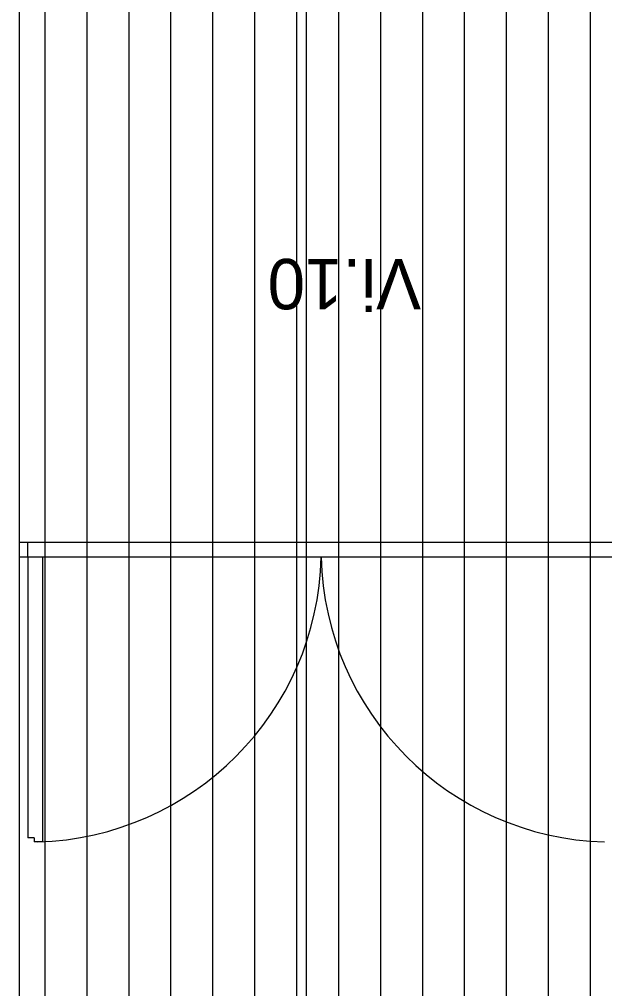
# Model space of a CAD drawing. Extents: x 1278 to 1356, y -253.7 to -224.
# Drawn here: x 1307.602 to 1308.997, y -239.071 to -236.76 of the extents above; entities that cross this region are included whole.
import ezdxf

# ---------------------------------------------------------------- set-up
doc = ezdxf.new("R2010")
doc.units = 0
for name, color, linetype in [('Level 10', 7, 'Continuous'), ('Level 13', 7, 'Continuous'), ('Level 4', 7, 'Continuous'), ('Level 40', 7, 'Continuous'), ('Level 65', 7, 'Continuous'), ('Level 93', 7, 'Continuous')]:
    doc.layers.add(name, color=color, linetype=linetype)

msp = doc.modelspace()

# ---------------------------------------------------------------- linework, layer by layer
at = {"layer": 'Level 10'}
for p, q in [((1307.6633, -243.574), (1307.6633, -235.1552)), ((1307.7633, -243.574), (1307.7633, -235.1552)), ((1307.8633, -243.574), (1307.8633, -235.1552)), ((1307.9633, -243.574), (1307.9633, -235.1552)), ((1308.0633, -243.574), (1308.0633, -235.1552)), ((1308.1633, -243.574), (1308.1633, -235.1552)), ((1308.2633, -243.574), (1308.2633, -235.1552)), ((1308.3633, -243.574), (1308.3633, -235.1552)), ((1308.4633, -243.574), (1308.4633, -235.1552)), ((1308.5633, -243.574), (1308.5633, -235.1552)), ((1308.6633, -243.574), (1308.6633, -235.1552)), ((1308.7633, -243.574), (1308.7633, -235.1552)), ((1308.8633, -243.574), (1308.8633, -235.1552)), ((1308.9633, -243.574), (1308.9633, -235.1552))]:
    msp.add_line(p, q, dxfattribs=at)
at = {"layer": 'Level 13'}
for p, q in [((1307.6219, -238.0075), (1307.6019, -238.0075)), ((1307.6219, -238.0075), (1307.6019, -238.0075)), ((1307.6219, -238.0075), (1307.6019, -238.0075)), ((1307.6219, -238.0425), (1307.6219, -238.0075)), ((1307.6219, -238.0425), (1307.6219, -238.0075)), ((1307.6219, -238.0425), (1307.6219, -238.0075)), ((1307.6219, -238.0425), (1307.6019, -238.0425)), ((1307.6219, -238.0425), (1307.6019, -238.0425)), ((1307.6219, -238.0425), (1307.6019, -238.0425)), ((1307.6219, -238.0425), (1307.6219, -238.7116)), ((1307.6219, -238.0425), (1307.6219, -238.7116)), ((1307.6219, -238.0425), (1307.6219, -238.7116)), ((1307.6569, -238.0425), (1307.6219, -238.0425)), ((1307.6569, -238.0425), (1307.6219, -238.0425)), ((1307.6569, -238.0425), (1307.6219, -238.0425)), ((1307.6569, -238.0425), (1307.6569, -238.7216)), ((1307.6569, -238.0425), (1307.6569, -238.7216)), ((1307.6569, -238.0425), (1307.6569, -238.7216)), ((1307.6369, -238.7116), (1307.6219, -238.7116)), ((1307.6369, -238.7116), (1307.6219, -238.7116)), ((1307.6369, -238.7116), (1307.6219, -238.7116)), ((1307.6369, -238.7116), (1307.6369, -238.7216)), ((1307.6369, -238.7116), (1307.6369, -238.7216)), ((1307.6369, -238.7116), (1307.6369, -238.7216)), ((1307.6569, -238.7216), (1307.6369, -238.7216)), ((1307.6569, -238.7216), (1307.6369, -238.7216)), ((1307.6569, -238.7216), (1307.6369, -238.7216))]:
    msp.add_line(p, q, dxfattribs=at)
at = {"layer": 'Level 4'}
for p, q in [((1309.0319, -238.0075), (1307.6106, -238.0075)), ((1309.0319, -238.0425), (1307.6456, -238.0425))]:
    msp.add_line(p, q, dxfattribs=at)
for centre, start, end in [((1307.6259, -238.0263), 271.6204, 358.6698), ((1309.0166, -238.0263), 181.3302, 268.3796)]:
    msp.add_arc(centre, 0.6955, start, end, dxfattribs=at)
at = {"layer": 'Level 65'}
msp.add_line((1307.6019, -243.574), (1307.6019, -235.1552), dxfattribs=at)
at = {"layer": 'Level 93'}
msp.add_line((1308.2865, -246.757), (1308.2865, -236.1407), dxfattribs=at)

# ---------------------------------------------------------------- texts
at = {"layer": 'Level 40'}
msp.add_text('Vi.10', height=0.12, rotation=180, dxfattribs=at).set_placement((1308.5594, -237.3313))

doc.saveas('drawing.dxf')
